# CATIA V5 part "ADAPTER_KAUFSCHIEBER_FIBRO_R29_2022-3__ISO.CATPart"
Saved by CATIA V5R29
Part number: ADAPTER_KAUFSCHIEBER_STARTPART
Revision: RELEASE@VERSION@1.0@02.03.2007
Property "Produktbezeichnung": "FCC AEC-HV 60-30°"
Property "Anzahl": 1
Property "Anzahl_spiegelbildlich": 0
Property "Werkstoff_Benennung": "1.1191"
Property "Rohmasse": 0 (mass)
Property "Zuschnittsmasse": 0 (mass)
Property "Fertigmasse": 0 (mass)
Property "Beschaffungsart": "B"
Property "ZSB_Blatt": 0
Property "Detail_Blatt": 0
Property "Lieferantenname": "FIBRO GmbH"
Property "Lieferantenauswahl": "bindend"
Property "Bestellnummer": "2016.24.006.30.2000.00"
Property "Waerme_Oberflaechenbehandlung": " "
Property "NC_Aenderung": "N"
Property "Ersatzteil": false
Property "Ersatzteil_k": 0
Property "Ersatzteil_s": 0
Property "Anfertigung": "A"
Property "Anfertigung_k": 0
Property "Anfertigung_s": 0
Property "Aenderungsindex": 0
Publications: "Axis_Referenz_in_Schieberrichtung", "Schieberdiagramm", "Fertigteil", "SCHIEBERKOERPER_SCHIEBERSTELLUNG_OFFEN_RELATIV_ZU_SCHIEBERBETT", "SCHIEBERKOERPER_SCHIEBERSTELLUNG_BEI_AUFTREFFEN_AUF_TREIBER", "SCHIEBERBETT_Fertigteil", "SCHIEBERBETT_Gussteil01_Anguss", "SCHIEBERBETT_Gussteil01_Fraesbearbeitung_1", "SCHIEBERBETT_Gussteil01_Fraesbearbeitung_2", "SCHIEBERBETT_Gussteil01_Bohrbearbeitung_1", "SCHIEBERBETT_Gussteil01_Bohrbearbeitung_2", "TREIBER_Fertigteil", "TREIBER_Gussteil02_Anguss", "TREIBER_Gussteil02_Fraesbearbeitung_1", "TREIBER_Gussteil02_Bohrbearbeitung_1", "TREIBER_Gussteil02_Bohrbearbeitung_2", "SCHIEBER_Montagefreiraum", "SCHIEBER_Bauraum", "INFO_Gewinde_Gussteil01", "INFO_D_Passbohrung_Gussteil01", "INFO_Tol_Passung_Gussteil01", "INFO_Gewinde_Gussteil02", "INFO_D_Passbohrung_Gussteil02", "INFO_Tol_Passung_Gusstei02", "INFO_Breite_Passfedernut_Gussteil01", "INFO_Tiefe_Passfedernut_Gussteil01", "INFO_Tol_Passfedernut_Gussteil01", "SCHIEBERBETT_BOHRSKETCH_GEWINDE", "SCHIEBERBETT_BOHRSKETCH_PASSUNGEN", "SCHIEBERBETT_BOHREBENE", "TREIBER_BOHRSKETCH_GEWINDE", "TREIBER_BOHRSKETCH_PASSUNGEN", "TREIBER_BOHREBENE", "SCHIEBERBETT_PASSFEDER", "INFO_Schieberwinkel", "INFO_Treiberwinkel", "INFO_Schieberhub", "INFO_Schieberart", "INFO_Produktbezeichnung", "INFO_Werkstoff_Benennung", "INFO_Rohmass", "INFO_Bestellnummer", "INFO_Lieferantenname", "INFO_Anzahl", "INFO_Rohmasse", "SKETCH_Passfeder1", "SKETCH_Passfeder2", "SKETCH_Passfeder3", "SKETCH_Passfeder4", "SCHIEBERKOERPER_BOHREBENE", "SCHIEBERKOERPER_BOHRSKETCH_AUSRICHTBOHRUNG", "SCHIEBERKOERPER_ZSB_Bearbeitung_Ausrichtflaeche", "SCHIEBERKOERPER_ZSB_Bearbeitung_Ausrichtbohrung"
Bounding box of the stored display mesh (mm): x 0 to 1950, y 0 to 429.656, z 0 to 1442.5
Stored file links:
  N:\B2\Normteile\K\2016\BAK_Adapter_2019\V_2019\ADAPTER_KAUFSCHIEBER_FIBRO_R29_2022-3__ISO.CATPart
  W:\KT_B5\Schneider_extern_47150\2007-02-12__Schieberadapter_alt\Kaufteilschieber_Stand_AK_07-08_11_2006\XX_XXX__ADAPTER_KAUFTEILSCHIEBER__123456789012.CATPart
  \\vhnfs271\ktkon\KT_B5\Schneider_extern_47150\2007-02-07__Adapter_Kaufteilschieber_R14\ADAPTER_KAUFTEILSCHIEBER_Vers11.CATPart
  N:\B2\Normteile\K\2016\BAK_Adapter_2019\V_2019\EXTRACT_INFO_PARAMETERS.xlsx
  N:\B2\Normteile\K\2016\24\CAD\V5\cm\260\2016.24.026.00.1000.00__CM.CATPart
  N:\B2\Normteile\K\2016\24\CAD\V5\cm\260\2016.24.026.75.1000.00__CM.CATPart
  N:\B2\Normteile\K\2016\24\CAD\V5\cm\260\2016.24.026.30.1000.00__CM.CATPart
  N:\B2\Normteile\K\2016\24\CAD\V5\cm\260\2016.24.026.65.1000.00__CM.CATPart
  N:\B2\Normteile\K\2016\15\008\cm\2016.15.008__CM__FCC_DM-HV_V00_ISO.CATPart
  N:\B2\Normteile\K\2016\15\008\cm\2016.15.008__CM__FCC_DM-HV.CATPart
  N:\B2\Normteile\K\2016\24\CAD\V5\cm\260\2016.24.026.45.1000.00__CM.CATPart
  N:\B2\Normteile\K\2016\24\CAD\V5\cm\220\2016.24.022.20.1000.00__CM.CATPart
  N:\B2\Normteile\K\2016\24\CAD\V5\cm\260\2016.24.026.40.1000.00__CM.CATPart
  N:\B2\Normteile\K\2016\24\CAD\V5\cm\260\2016.24.026.20.1000.00__CM.CATPart
  N:\B2\Normteile\K\2016\24\CAD\V5\cm\260\2016.24.026.10.1000.00__CM.CATPart
  N:\B2\Normteile\K\2016\24\CAD\V5\cm\260\2016.24.026.60.1000.00__CM.CATPart
  N:\B2\Normteile\K\2016\24\CAD\V5\cm\026\2016.24.026.10.1000.00__CM.CATPart
  N:\B2\Normteile\K\2016\24\CAD\V5\cm\008\2016.24.008.75.1000.00__CM.CATPart
  G:\Produkte\pg_k\2016\2016_25__neu_ab_GJ_2018\V5\cm\070\2016.25.07x.05.x000.02__CM.CATPart
  N:\B2\Normteile\K\2016\24\CAD\V5\cm\006\2016.24.006.30.2000.00__CM.CATPart
  N:\B2\Normteile\K\2016\15\016\cm\2016.15.016__CM__FCC_DM-HV_V00_ISO.CATPart
  N:\B2\Normteile\K\2016\15\016\cm\2016.15.016__CM__FCC_DM-HV.CATPart
  N:\B2\Normteile\K\2016\24\CAD\V5\cm\011\2016.24.011.10.1000.00__CM.CATPart
  N:\B2\Normteile\K\2016\24\CAD\V5\022\cm_parametric\2016.24.022__CM__FCC_AEC-HV__ADAPTER_COMPATIBLE.CATPart
  N:\B2\Normteile\K\2016\24\CAD\V5\026\cm_parametric\2016.24.026__CM__FCC_AEC-HV__ADAPTER_COMPATIBLE.CATPart
  N:\B2\Normteile\K\2016\24\CAD\V5\033\cm_parametric\2016.24.033__CM__FCC_AEC-HV__ADAPTER_COMPATIBLE.CATPart
  N:\B2\Normteile\K\2016\24\CAD\V5\040\cm_parametric\2016.24.040__CM__FCC_AEC-HV__ADAPTER_COMPATIBLE.CATPart
  N:\B2\Normteile\K\2016\24\CAD\V5\050\cm_parametric\2016.24.050__CM__FCC_AEC-HV__ADAPTER_COMPATIBLE.CATPart
  N:\B2\Normteile\K\2016\24\CAD\V5\060\cm_parametric\2016.24.060__CM__FCC_AEC-HV__ADAPTER_COMPATIBLE.CATPart
  N:\B2\Normteile\K\2016\24\CAD\V5\006\cm_parametric\2016.24.006__CM__FCC_AEC-HV__V00_ISO.CATPart
  N:\B2\Normteile\K\2016\15\011\cm\2016.15.011__CM__FCC_DM-HV.CATPart
  N:\B2\Normteile\K\2016\15\022\cm\2016.15.022__CM__FCC_DM-HV.CATPart
  N:\B2\Normteile\K\2016\15\031\cm\2016.15.031__CM__FCC_DM-HV.CATPart
  N:\B2\Normteile\K\2016\15\040\cm\2016.15.040__CM__FCC_DM-HV.CATPart
  G:\SApp\Anwendungsberatung\210224__BMW_ZSB_Ausrichtbohrung\CAD\ADAPTER_KAUFSCHIEBER_FIBRO_R28_2021__BETA_A_STEP1.CATPart
  N:\B2\Normteile\K\2016\24\CAD\V5\008\cm_parametric\2016.24.008__CM__FCC_AEC-HV__V00_ISO.CATPart
  N:\B2\Normteile\K\2016\24\CAD\V5\033\cm_parametric\2016.24.033__CM__FCC_AEC-HV__V00_ISO.CATPart
  N:\B2\Normteile\K\2016\15\008\cm\2016.15.008__CM__FCC_DM-HV_V02_ISO.CATPart
  N:\B2\Normteile\K\2016\15\011\cm\2016.15.011__CM__FCC_DM-HV_V02_ISO.CATPart
  N:\B2\Normteile\K\2016\15\016\cm\2016.15.016__CM__FCC_DM-HV_V02_ISO.CATPart
  N:\B2\Normteile\K\2016\15\022\cm\2016.15.022__CM__FCC_DM-HV_V02_ISO.CATPart
  N:\B2\Normteile\K\2016\15\031\cm\2016.15.031__CM__FCC_DM-HV_V02_ISO.CATPart
  N:\B2\Normteile\K\2016\15\040\cm\2016.15.040__CM__FCC_DM-HV_V02_ISO.CATPart
  N:\B2\Normteile\K\2016\24\CAD\V5\011\cm_parametric\2016.24.011__CM__FCC_AEC-HV__V00_ISO.CATPart
  N:\B2\Normteile\K\2016\24\CAD\V5\015\cm_parametric\2016.24.015__CM__FCC_AEC-HV__V00_ISO.CATPart
  N:\B2\Normteile\K\2016\24\CAD\V5\018\cm_parametric\2016.24.018__CM__FCC_AEC-HV__V00_ISO.CATPart
  N:\B2\Normteile\K\2016\24\CAD\V5\022\cm_parametric\2016.24.022__CM__FCC_AEC-HV__V00_ISO.CATPart
  N:\B2\Normteile\K\2016\24\CAD\V5\026\cm_parametric\2016.24.026__CM__FCC_AEC-HV__V00_ISO.CATPart
  N:\B2\Normteile\K\2016\24\CAD\V5\040\cm_parametric\2016.24.040__CM__FCC_AEC-HV__V00_ISO.CATPart
  N:\B2\Normteile\K\2016\24\CAD\V5\050\cm_parametric\2016.24.050__CM__FCC_AEC-HV__V00_ISO.CATPart
  N:\B2\Normteile\K\2016\24\CAD\V5\060\cm_parametric\2016.24.060__CM__FCC_AEC-HV__V00_ISO.CATPart
  N:\B2\Normteile\K\2016\25  #neu_ab_GJ_2018#\V5\cm\070\2016.25.07x.00.x000.02__CM.CATPart
  N:\B2\Normteile\K\2016\25  #neu_ab_GJ_2018#\V5\cm\070\2016.25.07x.05.x000.02__CM.CATPart
  N:\B2\Normteile\K\2016\25  #neu_ab_GJ_2018#\V5\cm\070\2016.25.07x.10.x000.02__CM.CATPart
  N:\B2\Normteile\K\2016\25  #neu_ab_GJ_2018#\V5\cm\070\2016.25.07x.15.x000.02__CM.CATPart
  N:\B2\Normteile\K\2016\25  #neu_ab_GJ_2018#\V5\cm\070\2016.25.07x.20.x000.02__CM.CATPart
  N:\B2\Normteile\K\2016\25  #neu_ab_GJ_2018#\V5\cm\070\2016.25.07x.25.x000.02__CM.CATPart
  N:\B2\Normteile\K\2016\25  #neu_ab_GJ_2018#\V5\cm\070\2016.25.07x.30.x000.02__CM.CATPart
  N:\B2\Normteile\K\2016\25  #neu_ab_GJ_2018#\V5\cm\070\2016.25.07x.35.x000.02__CM.CATPart
  N:\B2\Normteile\K\2016\25  #neu_ab_GJ_2018#\V5\cm\070\2016.25.07x.40.x000.02__CM.CATPart
  N:\B2\Normteile\K\2016\25  #neu_ab_GJ_2018#\V5\cm\070\2016.25.07x.45.x000.02__CM.CATPart
  N:\B2\Normteile\K\2016\25  #neu_ab_GJ_2018#\V5\cm\070\2016.25.07x.50.x000.02__CM.CATPart
  N:\B2\Normteile\K\2016\25  #neu_ab_GJ_2018#\V5\cm\070\2016.25.07x.55.x000.02__CM.CATPart
  N:\B2\Normteile\K\2016\25  #neu_ab_GJ_2018#\V5\cm\070\2016.25.07x.60.x000.02__CM.CATPart
  N:\B2\Normteile\K\2016\25  #neu_ab_GJ_2018#\V5\cm\070\2016.25.07x.65.x000.02__CM.CATPart
  N:\B2\Normteile\K\2016\25  #neu_ab_GJ_2018#\V5\cm\070\2016.25.07x.70.x000.02__CM.CATPart
  N:\B2\Normteile\K\2016\25  #neu_ab_GJ_2018#\V5\cm\070\2016.25.07x.75.x000.02__CM.CATPart
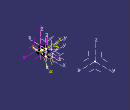
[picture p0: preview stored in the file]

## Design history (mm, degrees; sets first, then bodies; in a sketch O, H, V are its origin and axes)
Parameters
  Variante = "2016.24.006.30.2000.00" {= External.id_number}
  INFO_Version_Ausgabe = "2022-3" {design table}
  INFO_Schieberhub = 30 mm {design table}
  INFO_Winkel_Arbeitsrichtung = 30 deg {design table}
  INFO_Winkel_Alpha = 60 deg {design table}
  INFO_Passfeder_im_Lieferumfang = true {design table}
  INFO_Winkel_Treiber = 30 deg {design table}
  INFO_Winkel_Schieberbett = 30 deg {design table}
  INFO_Schieberart = "oben" {design table}
  group "Anschlussgeometrie"
    FP_Aufmass = 10 mm
    group "Schieberbett"
      cb_l = 205 mm {design table}
      cb_w = 60 mm {design table}
      cb_backup_thrust = true {design table}
      cb_clearance_backup_thrust = true {design table}
      FP_cb_Ueberstand_Spiegel = 15 mm
      FP_cb_Kraftabfangung = "Gussschulter"
      FP_cb_Hoehe_Schulter = 110 mm {design table}
      FP_cb_Breite_Schulter = 60 mm {design table}
      FP_cb_Freimachung_Schulter = "mit Freimachung"
      FP_cb_Gewindetiefe = 18 mm {design table}
      FP_cb_Gewindeauslauf = 8.3 mm {design table}
      FP_cb_Tiefe_Passbohrung = 15 mm {design table}
      FP_cb_Verlaengerung_Fraesung_Passfeder_laengs = 0 mm
      FP_cb_Verlaengerung_Fraesung_Passfeder_quer = 20 mm
      FP_cb_Fraeshoehe = 100 mm
    group "Treiber"
      cd_l = 125 mm {design table}
      cd_w = 60 mm {design table}
      cd_backup_thrust = true {design table}
      cd_clearance_backup_thrust = true {design table}
      FP_cd_Ueberstand_Spiegel = 10 mm
      FP_cd_Kraftabfangung = "Gussschulter"
      FP_cd_Hoehe_Schulter = 22 mm {design table}
      FP_cd_Breite_Schulter = 60 mm {design table}
      FP_cd_Freimachung_Schulter = "mit Freimachung"
      FP_cd_Gewindetiefe = 15 mm {design table}
      FP_cd_Gewindeauslauf = 7.3 mm {design table}
      FP_cd_Tiefe_Passbohrung = 15 mm {design table}
      FP_cd_Verlaengerung_Fraesung_Passfeder_quer = 20 mm
      FP_cd_Fraeshoehe = 100 mm
  group "Bohrbearbeitung"
    INFO_Gewinde_Gussteil01 = "M12" {design table}
    INFO_D_Passbohrung_Gussteil01 = 10 mm {design table}
    INFO_Tol_Passung_Gussteil01 = "H7" {design table}
    INFO_Gewinde_Gussteil02 = "M10" {design table}
    INFO_D_Passbohrung_Gussteil02 = 10 mm {design table}
    INFO_Tol_Passung_Gusstei02 = "H7" {design table}
  group "Fraesbearbeitung"
    INFO_Breite_Passfedernut_Gussteil01 = 25 mm {design table}
    INFO_Tiefe_Passfedernut_Gussteil01 = 10 mm {design table}
    INFO_Tol_Passfedernut_Gussteil01 = "H7" {design table}
  group "ZSB_Referenzbohrung"
    arx = 200 mm {design table}
    ary = 24 mm {design table}
    arz = 20 mm {design table}
  group "Translation_Schiebereinheit"
    External.Translation_Schiebereinheit_in_X = 0 mm
    External.Translation_Schiebereinheit_in_Y = 0 mm
    External.Translation_Schiebereinheit_in_Z = 0 mm
  group "Stueckliste"
    Positionsnummer = ""
    Identnummer = ""
    Produktbezeichnung = "FCC AEC-HV 60-30°" {design table}
    Anzahl = 1
    Anzahl_spiegelbildlich = 0
    Materialgruppe = ""
    Bemerkungskuerzel = ""
    Werkstoff_ID = ""
    Werkstoff_Benennung = "1.1191" {design table}
    Rohmass = "" {design table}
    Zuschnittsmass = ""
    Fertigmass = ""
    Rohmasse = 0 (mass) {design table}
    Zuschnittsmasse = 0 (mass)
    Fertigmasse = 0 (mass)
    Beschaffungsart = "B"
    DIN_ISO_Norm = ""
    Euro_Norm = ""
    Bauvorschrift_bzw_Werks_oder_Norm_Blatt = ""
    Lagernummer = ""
    Bezugsort = ""
    ZSB_Blatt = 0
    Detail_Blatt = 0
    Lieferantenname = "FIBRO GmbH"
    Lieferantennummer = ""
    Lieferantenauswahl = "bindend"
    Preiskategorie = ""
    Bestellnummer = "2016.24.006.30.2000.00" {= External.id_number}
    Sachmerkmale = ""
    Waerme_Oberflaechenbehandlung = " "
    Zusatzinfo = "" {design table}
    Hinweis = ""
    Verbaut_an_Pos_Nr = ""
    Symmetrie = ""
    NC_Aenderung = "N"
    Ersatzteil = false
    Ersatzteil_k = 0
    Ersatzteil_s = 0
    Anfertigung = "A"
    Anfertigung_k = 0
    Anfertigung_s = 0
    Langlaeufer = ""
    Aenderungsindex = 0
  group "Parameter_Schieberhersteller"
    factor = 1 {design table}
    sp = 30 mm {design table}
    ss = 30 mm {design table}
    cb_kl_h = 19 mm {design table}
    cb_kl_t = 10 mm {design table}
    cb_kl_l = 59 mm {design table}
    cb_kl1_x = 50 mm {design table}
    cb_kl1_activity = false {design table}
    cb_kl2_x = 100 mm {design table}
    cb_kl2_activity = false {design table}
    cb_kc_l = 59 mm {design table}
    cb_kc1_x = 62.5 mm {design table}
    cb_kc1_y = 0 mm {design table}
    cb_kc2_activity = false {design table}
    cd_kc_l = 50 mm {design table}
    cd_kc1_x = 30 mm {design table}
    cd_kc1_y = 35 mm {design table}
    cd_kc1_activity = false {design table}
    cd_kc2_activity = false {design table}
    type = "aerial cam unit" {design table}
    change_description = "assembly reference hole added, 2016.26 series added"
External parameters (linked from other documents)
  External.id_number = "2016.24.006.30.2000.00"
AxisSystem1 "Absolute Axis System": origin (0, 0, 0), X (1, 0, 0), Y (0, 1, 0), Z (0, 0, 1)
TTRSSet1
f4a2d38f3ddc11d3a929006094b99c4b_11 "CATTPSSet"
Set1 "ELEMENTE_FUER_REPLACE"
  AxisSystem2 "Dummy_AP_Axis_zum_Ersetzen": origin (1700, 0, 1200), X (1, 0, 0), Y (0, 1, 0), Z (0, 0, 1)
  Line1 "Dummy_Schieberrichtung_zum_Ersetzen": stored without definition
  AxisSystem3 "Axis_Horizontal_im_Einfuegepunkt_zum_Ersetzen": origin (1850, 180, 1312), X (0, 1, 0), Y (-1, 0, 0), Z (0, 0, 1)
  AxisSystem4 "Axis_Schieberrichtung_im_Einfuegepunkt_zum_Ersetzen": origin (1850, 180, 1312), X (0, 0.5, -0.866), Y (-1, 0, 0), Z (0, 0.866, 0.5)
Set2 "HILFSELEMENTE_POSITIONIERUNG"
  Plane1 "Plane_Hoehe_Einfuegepunkt_Schieber_zu_AP": type Offset, RefPlane XY plane of AxisSystem2, Offset 112
  Sketch1 "Sketch_Lage_Einfuegepunkt_Schieber_in_XOY" on Plane1, origin (1700, 0, 1312), H (1, 0, 0), V (0, 1, 0)
    point P1 (150, 180)
    line L1 (150, 280) -> (150, 80)
    reference projected line E1 (0, 0) -> (0, 246.2019) from Line1
    distance P1 H = 180
    distance P1 V = 150
    length L1 = 200
    midpoint: P1 L1
    parallelism: L1 E1
  Point1 "Absolute_Origin_Schiebereinheit": (0 {= External.Translation_Schiebereinheit_in_X}, 0 {= External.Translation_Schiebereinheit_in_Y}, 0 {= External.Translation_Schiebereinheit_in_Z})
  AxisToAxis1 "Lokale_Origin_Schiebereinheit": ToTransfor Point1, AxisOrigin AxisSystem1, Axis AxisSystem4
Set3 "HILFSELEMENTE_ACHSEN"
  Line2 "Schieberrichtung": type Angle, RefPoint vertex [YZ plane of AxisSystem3 | ZX plane of AxisSystem3 | XY plane of AxisSystem3], Curve edge [XY plane of AxisSystem3 | ZX plane of AxisSystem3], Support ZX plane of AxisSystem3, Start 0, End 20, Angle -30 {= -INFO_Winkel_Treiber}
  Line3 "Y-Richtung": type Normal, RefPoint vertex [YZ plane of AxisSystem3 | ZX plane of AxisSystem3 | XY plane of AxisSystem3], RefSkin ZX plane of AxisSystem3, Start 0, End 20
Set4 "ACHSENSYSTEME_REFERENZ_SCHIEBERHERSTELLER"
  AxisSystem5 "Axis_Referenz_in_Schieberrichtung": origin (1850, 180, 1312), X (0, 0.5, -0.866), Y (-1, 0, 0), Z (0, 0.866, 0.5)
  Line4 "X-Richtung_Axis_Referenz_horizontal": type Angle, RefPoint vertex [YZ plane of AxisSystem5 | ZX plane of AxisSystem5 | XY plane of AxisSystem5], Curve edge [ZX plane of AxisSystem5 | YZ plane of AxisSystem5], Support ZX plane of AxisSystem5, Start 0, End 20, Angle 30 {= INFO_Winkel_Arbeitsrichtung}
  AxisSystem6 "Axis_Referenz_horizontal": origin (1850, 180, 1312), X (0, 1, 0), Y (-1, 0, 0), Z (0, 0, 1)
Set5 "Diagramm"
  Sketch2 "Schieberdiagramm" on ZX plane of AxisSystem6, origin (1850, 180, 1312), H (0, 1, 0), V (0, 0, 1), geometry linked from another document
Set6 "SCHIEBERKOERPER_HILFSELEMENTE"
  Set7 "reference elements"
    Set8 "origin"
      AxisSystem7: origin (-25, 0, 210), X (1, 0, 0), Y (0, -1, 0), Z (0, 0, -1)
      AxisSystem8: origin (136.258, 0, 88.5), X (-0.5, 0, -0.866), Y (0, -1, 0), Z (-0.866, 0, 0.5)
      AxisSystem9: origin (0, 0, 0), X (-1, 0, 0), Y (0, -1, 0), Z (0, 0, 1)
    Set9 "translated"
      AxisToAxis2 "cam base": ToTransfor AxisSystem7, AxisOrigin AxisSystem8, Axis AxisSystem5
      AxisToAxis3 "cam driver": ToTransfor AxisSystem9, AxisOrigin AxisSystem8, Axis AxisSystem5
      AxisToAxis4 "sp_assembly_reference_hole_tr": ToTransfor sketch element, AxisOrigin AxisSystem8, Axis AxisSystem5
    Set10 "relative positions"
      Line5 "spring direction": type Angle, RefPoint vertex [YZ plane of AxisSystem5 | ZX plane of AxisSystem5 | XY plane of AxisSystem5], Curve Line4, Support ZX plane of AxisSystem5, Start 0, End 30 {= ss}, Angle 30 {= factor *INFO_Winkel_Schieberbett}
      Translate1 "1": Direction edge [ZX plane of AxisSystem6 | YZ plane of AxisSystem6], Length 30 {= factor *sp}, ToTransfor vertex [YZ plane of AxisSystem6 | ZX plane of AxisSystem6 | XY plane of AxisSystem6]
      Translate2 "3": Direction Line5, Length 30 {= ss}, ToTransfor Translate1
    Set11 "PMI"
      Extract1 "anchor point": ExtractElem vertex [YZ plane of AxisSystem6 | ZX plane of AxisSystem6 | XY plane of AxisSystem6]
      Plane2 "support plane": type OffsetPt, RefPlane ZX plane of AxisSystem6, RefPoint Extract1
      Line6 "orientation": type PtDir, RefPoint Extract1, Direction edge [XY plane of AxisSystem6 | ZX plane of AxisSystem6], Start -50, End 50
    Set12 "Bezugselemente ZSB-Bearbeitung step1"
      Plane3 "PLN_milling_assembly_refrence_hole step1": type Offset, RefPlane XY plane of AxisSystem9, Offset 20 {= arz}
      Sketch3 "assembly_reference_hole" on Plane3, origin (0, 0, 20), H (0, -1, 0), V (-1, 0, 0)
        point P1 (24, -200)
        point P2 (-24, -200)
        construction circle A1 centre (24, -200) radius 4
        point P3 (24, -200)
        distance V P1 = 24 {= ary}
        distance H P1 = 200 {= arx}
        radius A1 = 4
        symmetry: P1 P2 V
        coincidence: P3 P1
Set13 "SCHIEBERKOERPER_BOHRSKIZZEN_UND_BOHREBENEN"
  AxisToAxis5 "SCHIEBERKOERPER_BOHREBENE": ToTransfor Plane3, AxisOrigin AxisSystem8, Axis AxisSystem5
  Sketch4 "SCHIEBERKOERPER_BOHRSKETCH_AUSRICHTBOHRUNG" on AxisToAxis5, origin (1850, 316.258, 1243.5), H (1, 0, 0), V (0, 1, 0), geometry linked from another document
Set14 "SCHIEBERBETT_HILFSELEMENTE"
  Set15 "interface"
    DatumPoint1 "Result of sp_screw_base": linked copy from another document
    DatumPoint2 "Result of sp_pin_base": linked copy from another document
    AxisToAxis6 "sp_screw_base": ToTransfor DatumPoint1, AxisOrigin AxisSystem8, Axis AxisSystem5
    AxisToAxis7 "sp_pin_base": ToTransfor DatumPoint2, AxisOrigin AxisSystem8, Axis AxisSystem5
    Sketch5 "key positions along" on Plane4, origin (1850, 341.258, 1433.5), H (0, 1, 0), V (-1, 0, 0)
      point P1 (-50, 0)
      point P2 (-100, 0)
      distance V P1 = 50 {= cb_kl1_x}
      distance P2 V = 100 {= cb_kl2_x}
      coincidence: P1 H, P2 H
    Sketch6 "key positions cross" on Plane4, origin (1850, 341.258, 1433.5), H (0, 1, 0), V (-1, 0, 0)
      point P1 (-62.5, 0)
      point P2 (-62.5, 0)
      distance V P1 = 62.5 {= cb_kc1_x}
      distance H P1 = 0 {= cb_kc1_y}
      symmetry: P1 P2 H
Set16 "SCHIEBERBETT_BOHRSKIZZEN_UND_BOHREBENEN"
  Plane4 "SCHIEBERBETT_BOHREBENE": type OffsetPt, RefPlane face of AxisToAxis2, RefPoint vertex [face of AxisToAxis2 | face of AxisToAxis2 | face of AxisToAxis2]
  Sketch7 "SCHIEBERBETT_BOHRSKETCH_GEWINDE" on face of AxisToAxis2, origin (1850, 341.258, 1433.5), H (0, 1, 0), V (-1, 0, 0), geometry linked from another document
  Sketch8 "SCHIEBERBETT_BOHRSKETCH_PASSUNGEN" on face of AxisToAxis2, origin (1850, 341.258, 1433.5), H (0, 1, 0), V (-1, 0, 0), geometry linked from another document
Set17 "TREIBER_HILFSELEMENTE"
  Set18 "interface"
    DatumPoint3 "Result of sp_screw_driver": linked copy from another document
    DatumPoint4 "Result of sp_pin_driver": linked copy from another document
    AxisToAxis8 "sp_screw_driver": ToTransfor DatumPoint3, AxisOrigin AxisSystem8, Axis AxisSystem5
    AxisToAxis9 "sp_pin_driver": ToTransfor DatumPoint4, AxisOrigin AxisSystem8, Axis AxisSystem5
    Sketch9 "key positions cross" on Plane5, origin (1850, 316.258, 1223.5), H (0, -1, 0), V (-1, 0, 0)
      point P1 (30, -35)
      point P2 (30, 35)
      distance V P1 = 30 {= cd_kc1_x}
      distance H P1 = 35 {= cd_kc1_y}
      symmetry: P1 P2 H
Set19 "TREIBER_BOHRSKIZZEN_UND_BOHREBENEN"
  Plane5 "TREIBER_BOHREBENE": type OffsetPt, RefPlane face of AxisToAxis3, RefPoint vertex [face of AxisToAxis3 | face of AxisToAxis3 | face of AxisToAxis3]
  Sketch10 "TREIBER_BOHRSKETCH_GEWINDE" on face of AxisToAxis3, origin (1850, 316.258, 1223.5), H (0, -1, 0), V (-1, 0, 0), geometry linked from another document
  Sketch11 "TREIBER_BOHRSKETCH_PASSUNGEN" on face of AxisToAxis3, origin (1850, 316.258, 1223.5), H (0, -1, 0), V (-1, 0, 0), geometry linked from another document
Body1 "SCHIEBERKOERPER_Fertigteil" (main body)
  Body2 "Rohteil"
    Body3 "Grundkoerper"
      Body4 "Result of cam slider"
        Solid1: linked copy from another document
      Assemble1: tool Body4
      AxisToAxis10: ToTransfor Assemble1, AxisOrigin AxisSystem8, Axis AxisSystem5
    Add1 "Grundkoerper": tool Body3
    Body5 "Gusskorrektur_Abzug"
    Remove1 "Gusskorrektur_Abzug": tool Body5
    Body6 "Gusskorrektur_Anguss"
    Add2 "Gusskorrektur_Anguss": tool Body6
    Body7 "Gusskorrektur_Freiguss"
    Remove2 "Gusskorrektur_Freiguss": tool Body7
    Body8 "Bearbeitungszugaben"
    Add3 "Bearbeitungszugaben": tool Body8, deactivated
  Add4 "Rohteil": tool Body2
  Body9 "Fraesbearbeitung"
  Remove3 "Fraesbearbeitung": tool Body9
  Body10 "Bohrbearbeitung"
  Remove4 "Bohrbearbeitung": tool Body10
  Body11 "ZSB_Bearbeitung"
  Remove5 "ZSB_Bearbeitung": tool Body11
Body12 "SCHIEBERKOERPER_SCHIEBERSTELLUNG_OFFEN_RELATIV_ZU_SCHIEBERBETT"
  Body13 "Result of SCHIEBERKOERPER_Fertigteil"
    Solid2: linked copy from another document
  Add5: tool Body13
  Translate3 "translate.1": Direction Line5, Length 30 {= ss}, ToTransfor Add5
Body14 "SCHIEBERKOERPER_SCHIEBERSTELLUNG_BEI_AUFTREFFEN_AUF_TREIBER"
  Body15 "Result of SCHIEBERKOERPER_Fertigteil"
    Solid3: linked copy from another document
  Add6: tool Body15
  Translate4 "translate.2": FirstPoint vertex [YZ plane of AxisSystem6 | ZX plane of AxisSystem6 | XY plane of AxisSystem6], SecondPoint Translate2, ToTransfor Add6
Body16 "SCHIEBERKOERPER_ZSB_Bearbeitung_Ausrichtflaeche"
  Sketch12 on AxisToAxis5, origin (1826, 116.258, 1243.5), H (-1, 0, 0), V (0, 1, 0)
    line L1 (-4.5, -45) -> (20.5, -45)
    line L2 (20.5, -45) -> (20.5, 25)
    line L3 (20.5, 25) -> (-4.5, 25)
    line L4 (-4.5, 25) -> (-4.5, -45)
    distance L4 V = 4.5
    horizontal: L1 H, L3 H
    vertical: L2 V, L4 V
  Pocket1: profile Sketch12, direction (0, 0, -1), length 20
  Fillet1: radius 13, on edge [face of Pocket1 from Sketch12.L4 | face of Pocket1 from Sketch12.L3]
  Mirror1: of the body so far, about face of AxisToAxis3
Body17 "SCHIEBERKOERPER_ZSB_Bearbeitung_Ausrichtbohrung"
  Sketch13 on AxisToAxis5, origin (1826, 116.258, 1243.5), H (1, 0, 0), V (0, 1, 0)
    point P1 (0, 0)
    coincidence: O P1
  Hole1: placed by Sketch13, at (1826, 116.258, 1243.5) direction (0, 0, 1), diameter 8, depth 15, V-bottom angle 120
  UserPattern1: of the body so far, copies 2, at the points of Sketch4
Body18 "SCHIEBERBETT_Fertigteil"
  Body19 "Result of cam base"
    Solid4: linked copy from another document
  Assemble2: tool Body19
  AxisToAxis11: ToTransfor Assemble2, AxisOrigin AxisSystem8, Axis AxisSystem5
Body20 "SCHIEBERBETT_PASSFEDER"
  Sketch14 on ZX plane of AxisSystem5, origin (1850, 180, 1312), H (0, 0.866, 0.5), V (0, 0.5, -0.866)
    line L1 (2, 0.5) -> (2.866, 0)
    point P2 (2.866, 0)
    line L2 (2.866, 0) -> (2, -0.5)
    line L3 (2, -0.5) -> (2, 0.5)
    reference projected line E1 through (0, 0) direction (0, 1) from edge [XY plane of AxisSystem5 | ZX plane of AxisSystem5]
    reference projected line E2 through (0, 0) direction (1, 0) from edge [ZX plane of AxisSystem5 | YZ plane of AxisSystem5]
    length L3 = 1
    length L2 = 1
    length L1 = 1
    distance L3 E1 = 2
    vertical: L3 V
    coincidence: P2 E2
  Shaft1 "Dummy_Passfeder": profile Sketch14, axis Sketch14.L3, angle 360, deactivated
  Sketch15 "SKETCH_Passfeder1" on Plane4, origin (1850, 291.258, 1433.5), H (0, 1, 0), V (-1, 0, 0)
    line L1 (-29.5, 0) -> (29.5, 0)
    length L1 = 59 {= cb_kl_l}
    midpoint: L1 O
    horizontal: L1 H
  Pad1: profile Sketch15, direction (0, 0, 1), length 9 {= cb_kl_h-cb_kl_t}, opposite side length 10 {= cb_kl_t}, thin wall 25 {= INFO_Breite_Passfedernut_Gussteil01}, deactivated
  Sketch16 "SKETCH_Passfeder2" on Plane4, origin (1850, 241.258, 1433.5), H (0, 1, 0), V (-1, 0, 0)
    line L1 (-29.5, 0) -> (29.5, 0)
    length L1 = 59 {= cb_kl_l}
    midpoint: L1 O
    horizontal: L1 H
  Pad2: profile Sketch16, direction (0, 0, 1), length 9 {= cb_kl_h-cb_kl_t}, opposite side length 10 {= cb_kl_t}, thin wall 25 {= INFO_Breite_Passfedernut_Gussteil01}, deactivated
  Sketch17 "SKETCH_Passfeder3" on Plane4, origin (1850, 278.758, 1433.5), H (0, 1, 0), V (-1, 0, 0)
    line L1 (0, -29.5) -> (0, 29.5)
    length L1 = 59 {= cb_kc_l}
    midpoint: L1 O
    vertical: L1 V
  Pad3: profile Sketch17, direction (0, 0, 1), length 9 {= cb_kl_h-cb_kl_t}, opposite side length 10 {= cb_kl_t}, thin wall 25 {= INFO_Breite_Passfedernut_Gussteil01}
  Sketch18 "SKETCH_Passfeder4" on Plane4, origin (1850, 278.758, 1433.5), H (0, 1, 0), V (-1, 0, 0)
    line L1 (0, -29.5) -> (0, 29.5)
    length L1 = 59 {= cb_kc_l}
    midpoint: L1 O
    vertical: L1 V
  Pad4: profile Sketch18, direction (0, 0, 1), length 9 {= cb_kl_h-cb_kl_t}, opposite side length 10 {= cb_kl_t}, thin wall 25 {= INFO_Breite_Passfedernut_Gussteil01}, deactivated
Body21 "SCHIEBERBETT_Gussteil01_Anguss"
  Sketch19 on face of AxisToAxis2, origin (1850, 341.258, 1433.5), H (0, 1, 0), V (0, 0, -1)
    point P1 (15, 0)
    point P2 (-220, 0)
    line L1 (-220, 0) -> (15, 0)
    distance P1 V = 15 {= FP_cb_Ueberstand_Spiegel}
    distance V P2 = 220 {= cb_l+FP_cb_Ueberstand_Spiegel}
    horizontal: L1 H
    coincidence: H L1
  Pad5: profile Sketch19, direction (-1, 0, 0), length 45 {= cb_w/2+FP_cb_Ueberstand_Spiegel}, mirrored extent, thin wall 10 {= FP_Aufmass}, second thickness 50
  Chamfer1: length 20 {= FP_cb_Ueberstand_Spiegel +5mm}, angle 45, on edge [face of Pad5 | end face of Pad5] (x2); edge [start face of Pad5 | face of Pad5] (x2)
  Thickness1 "manuelle Korrektur vorn": Face face of Pad5, Thickness 0
  Thickness2 "manuelle Korrektur seitlich": Face (end face of Pad5; start face of Pad5), Thickness 0
  Thickness3 "manuelle Korrektur hinten": Face face of Pad5, Thickness 0
  Body22 "Gussschulter"
    Sketch20 on face of AxisToAxis2, origin (1850, 341.258, 1323.5), H (0, 1, 0), V (0, 0, -1)
      point P1 (0, -50)
      point P2 (0, -170)
      line L1 (0, -170) -> (0, -50)
      distance P2 H = 170 {= FP_cb_Hoehe_Schulter+60mm}
      distance P1 H = 50
      coincidence: V L1
      vertical: L1 V
    Sketch21 on face of AxisToAxis2, origin (1850, 341.258, 1433.5), H (0, 1, 0), V (0, 0, -1)
      point P1 (0, -50)
      point P2 (0, 110)
      line L1 (0, 110) -> (0, -50)
      distance P1 H = 50
      distance H P2 = 110 {= FP_cb_Hoehe_Schulter}
      coincidence: V L1
      vertical: L1 V
    Pad6: profile Sketch21, direction (-1, 0, 0), length 30 {= FP_cb_Breite_Schulter /2}, mirrored extent, thin wall 10 {= FP_Aufmass}, second thickness 60
    Pocket2: profile Sketch20, direction (1, 0, 0), through (limit type 3), opposite side through (limit type 3), thin wall 20, second thickness 50
  Assemble3 "Gussschulter": tool Body22
Body23 "SCHIEBERBETT_Gussteil01_Fraesbearbeitung_1"
  Body24
    Sketch22 on face of AxisToAxis2, origin (1850, 341.258, 1433.5), H (0, 1, 0), V (0, 0, -1)
      point P1 (0, 0)
      point P2 (-230, 0)
      line L1 (-230, 0) -> (0, 0)
      distance V P2 = 230 {= cb_l+FP_cb_Ueberstand_Spiegel +10mm}
      horizontal: L1 H
      coincidence: H L1, V P1
    Pocket3: profile Sketch22, direction (1, 0, 0), length 60 {= cb_w /2+FP_cb_Ueberstand_Spiegel +15mm}, mirrored extent, thin wall 110 {= FP_Aufmass + FP_cb_Fraeshoehe}
    Fillet2: radius 20, on edge [end face of Pocket3 | face of Pocket3] (x2); edge [face of Pocket3 | start face of Pocket3] (x2)
  Assemble4: tool Body24
  Body25
    Sketch23 on face of AxisToAxis2, origin (1850, 341.258, 1433.5), H (0, 1, 0), V (0, 0, -1)
      point P1 (0, 0)
      point P2 (0, 120)
      line L1 (0, 120) -> (0, 0)
      distance H P2 = 120 {= FP_cb_Hoehe_Schulter +10mm}
      coincidence: V P1
      vertical: L1 V
    Pocket4: profile Sketch23, direction (1, 0, 0), length 60 {= FP_cb_Breite_Schulter  /2+FP_cb_Ueberstand_Spiegel +15mm}, mirrored extent, thin wall 30 {= FP_Aufmass +20mm}
    Fillet3: radius 20, on edge [start face of Pocket4 | face of Pocket4]; edge [face of Pocket4 | end face of Pocket4]
  Assemble5: tool Body25
Body26 "SCHIEBERBETT_Gussteil01_Fraesbearbeitung_2"
  Sketch24 on ZX plane of AxisSystem5, origin (1850, 180, 1312), H (0, 0.866, 0.5), V (0, 0.5, -0.866)
    line L1 (2, 0.5) -> (2.866, 0)
    point P2 (2.866, 0)
    line L2 (2.866, 0) -> (2, -0.5)
    line L3 (2, -0.5) -> (2, 0.5)
    length L3 = 1
    length L2 = 1
    length L1 = 1
    distance L3 V = 2
    coincidence: P2 H
    vertical: L3 V
  Groove1 "Dummy_Passfedernut": profile Sketch24, axis Sketch24.L3, angle 360, deactivated
  Body27 "key.1"
    Pocket5: profile Sketch15, direction (0, 0, 1), length 10 {= INFO_Tiefe_Passfedernut_Gussteil01}, thin wall 25 {= INFO_Breite_Passfedernut_Gussteil01}
    Thickness4: Face (face of Pocket5; face of Pocket5), Thickness 12 {= (INFO_Breite_Passfedernut_Gussteil01 -1mm)/2+FP_cb_Verlaengerung_Fraesung_Passfeder_laengs}
    Fillet4: radius 12 {= (INFO_Breite_Passfedernut_Gussteil01 -1mm)/2}, on edge [face of Pocket5 | face of Pocket5] (x4)
  Assemble6 "key.1": tool Body27, deactivated
  Body28 "key.2"
    Pocket6: profile Sketch16, direction (0, 0, 1), length 10 {= INFO_Tiefe_Passfedernut_Gussteil01}, thin wall 25 {= INFO_Breite_Passfedernut_Gussteil01}
    Thickness5: Face (face of Pocket6; face of Pocket6), Thickness 12 {= (INFO_Breite_Passfedernut_Gussteil01 -1mm)/2+FP_cb_Verlaengerung_Fraesung_Passfeder_laengs}
    Fillet5: radius 12 {= (INFO_Breite_Passfedernut_Gussteil01 -1mm)/2}, on edge [face of Pocket6 | face of Pocket6] (x4)
  Assemble7 "key.2": tool Body28, deactivated
  Body29 "key.3"
    Pocket7: profile Sketch17, direction (0, 0, 1), length 10 {= INFO_Tiefe_Passfedernut_Gussteil01}, thin wall 25 {= INFO_Breite_Passfedernut_Gussteil01}
    Thickness6: Face (face of Pocket7; face of Pocket7), Thickness 32 {= (INFO_Breite_Passfedernut_Gussteil01 -1mm)/2+FP_cb_Verlaengerung_Fraesung_Passfeder_quer}
    Fillet6: radius 12 {= (INFO_Breite_Passfedernut_Gussteil01 -1mm)/2}, on edge [face of Pocket7 | face of Pocket7] (x4)
  Assemble8 "key.3": tool Body29
  Body30 "key.4"
    Pocket8: profile Sketch18, direction (0, 0, 1), length 10 {= INFO_Tiefe_Passfedernut_Gussteil01}, thin wall 25 {= INFO_Breite_Passfedernut_Gussteil01}
    Thickness7: Face (face of Pocket8; face of Pocket8), Thickness 32 {= (INFO_Breite_Passfedernut_Gussteil01 -1mm)/2+FP_cb_Verlaengerung_Fraesung_Passfeder_quer}
    Fillet7: radius 12 {= (INFO_Breite_Passfedernut_Gussteil01 -1mm)/2}, on edge [face of Pocket8 | face of Pocket8] (x4)
  Assemble9 "key.4": tool Body30, deactivated
Body31 "SCHIEBERBETT_Gussteil01_Bohrbearbeitung_1"
  Sketch25 on Plane4, origin (1867.5, 326.258, 1433.5), H (1, 0, 0), V (0, -1, 0)
    point P1 (0, 0)
    coincidence: P1 O
  Hole2: placed by Sketch25, at (1867.5, 326.258, 1433.5) direction (0, 0, 1), diameter 10.2, depth 26.3 {= FP_cb_Gewindetiefe+FP_cb_Gewindeauslauf}, V-bottom angle 120, threaded "M12", thread diameter 12, thread depth 18 {= FP_cb_Gewindetiefe}, pitch 1.75
  UserPattern2: of Hole2, copies 4, at the points of Sketch7
Body32 "SCHIEBERBETT_Gussteil01_Bohrbearbeitung_2"
  Sketch26 on Plane4, origin (1850, 326.258, 1433.5), H (1, 0, 0), V (0, -1, 0)
    point P1 (0, 0)
    coincidence: P1 O
  Hole3: placed by Sketch26, at (1850, 326.258, 1433.5) direction (0, 0, 1), diameter 10 {= INFO_D_Passbohrung_Gussteil01}, depth 15 {= FP_cb_Tiefe_Passbohrung}, V-bottom angle 120
  UserPattern3: of Hole3, copies 2, at the points of Sketch8
Body33 "TREIBER_Fertigteil"
  Body34 "Result of cam driver"
    Solid5: linked copy from another document
  Assemble10: tool Body34
  AxisToAxis12: ToTransfor Assemble10, AxisOrigin AxisSystem8, Axis AxisSystem5
Body35 "TREIBER_Gussteil02_Anguss"
  Sketch27 on face of AxisToAxis3, origin (1850, 316.258, 1223.5), H (0, 1, 0), V (0, 0, 1)
    point P1 (10, 0)
    point P2 (-135, 0)
    line L1 (-135, 0) -> (10, 0)
    distance P1 V = 10 {= FP_cd_Ueberstand_Spiegel}
    distance V P2 = 135 {= cd_l+FP_cd_Ueberstand_Spiegel}
    horizontal: L1 H
    coincidence: H L1
  Pad7: profile Sketch27, direction (1, 0, 0), length 40 {= cd_w/2+FP_cd_Ueberstand_Spiegel}, mirrored extent, thin wall 10 {= FP_Aufmass}, second thickness 50
  Chamfer2: length 15 {= FP_cd_Ueberstand_Spiegel +5mm}, angle 45, on edge [face of Pad7 | end face of Pad7] (x2); edge [start face of Pad7 | face of Pad7] (x2)
  Thickness8 "manuelle Korrektur vorn": Face face of Pad7, Thickness 0
  Thickness9 "manuelle Korrektur seitlich": Face (end face of Pad7; start face of Pad7), Thickness 0
  Thickness10 "manuelle Korrektur hinten": Face face of Pad7, Thickness 0
  Body36 "Gussschulter"
    Sketch28 on face of AxisToAxis3, origin (1850, 316.258, 1245.5), H (0, 1, 0), V (0, 0, 1)
      point P1 (0, -50)
      point P2 (0, -82)
      line L1 (0, -82) -> (0, -50)
      distance P2 H = 82 {= FP_cd_Hoehe_Schulter+60mm}
      distance P1 H = 50
      coincidence: V L1
      vertical: L1 V
    Sketch29 on face of AxisToAxis3, origin (1850, 316.258, 1223.5), H (0, 1, 0), V (0, 0, 1)
      point P1 (0, -50)
      point P2 (0, 22)
      line L1 (0, 22) -> (0, -50)
      distance P1 H = 50
      distance H P2 = 22 {= FP_cd_Hoehe_Schulter}
      coincidence: V L1
      vertical: L1 V
    Pad8: profile Sketch29, direction (1, 0, 0), length 30 {= FP_cd_Breite_Schulter /2}, mirrored extent, thin wall 10 {= FP_Aufmass}, second thickness 60
    Pocket9: profile Sketch28, direction (-1, 0, 0), through (limit type 3), opposite side through (limit type 3), thin wall 20, second thickness 50
  Assemble11 "Gussschulter": tool Body36
Body37 "TREIBER_Gussteil02_Fraesbearbeitung_1"
  Body38 "interface"
    Body39
      Sketch30 on face of AxisToAxis3, origin (1850, 316.258, 1223.5), H (0, 1, 0), V (0, 0, 1)
        point P1 (0, 0)
        point P2 (-145, 0)
        line L1 (-145, 0) -> (0, 0)
        distance V P2 = 145 {= cd_l+FP_cd_Ueberstand_Spiegel +10mm}
        horizontal: L1 H
        coincidence: H L1, V P1
      Pocket10: profile Sketch30, direction (-1, 0, 0), length 55 {= cd_w /2+FP_cd_Ueberstand_Spiegel +15mm}, mirrored extent, thin wall 110 {= FP_Aufmass + FP_cd_Fraeshoehe}
      Fillet8: radius 20, on edge [end face of Pocket10 | face of Pocket10] (x2); edge [face of Pocket10 | start face of Pocket10] (x2)
    Assemble12: tool Body39
    Body40
      Sketch31 on face of AxisToAxis3, origin (1850, 316.258, 1223.5), H (0, 1, 0), V (0, 0, 1)
        point P1 (0, 0)
        point P2 (0, 32)
        line L1 (0, 32) -> (0, 0)
        distance H P2 = 32 {= FP_cd_Hoehe_Schulter +10mm}
        coincidence: V P1
        vertical: L1 V
      Pocket11: profile Sketch31, direction (-1, 0, 0), length 55 {= FP_cd_Breite_Schulter  /2+FP_cd_Ueberstand_Spiegel +15mm}, mirrored extent, thin wall 30 {= FP_Aufmass +20mm}
      Fillet9: radius 20, on edge [face of Pocket11 | end face of Pocket11]; edge [start face of Pocket11 | face of Pocket11]
    Assemble13: tool Body40
  Assemble14 "interface": tool Body38
  Body41 "key.5"
    Sketch32 "SKETCH_Passfeder5" on Plane5, origin (1885, 286.258, 1223.5), H (0, -1, 0), V (-1, 0, 0)
      line L1 (0, -25) -> (0, 25)
      length L1 = 50 {= cd_kc_l}
      midpoint: L1 O
      vertical: L1 V
    Pocket12: profile Sketch32, direction (0, 0, -1), length 10 {= INFO_Tiefe_Passfedernut_Gussteil01}, thin wall 25 {= INFO_Breite_Passfedernut_Gussteil01}
    Thickness11: Face (face of Pocket12; face of Pocket12), Thickness 32 {= (INFO_Breite_Passfedernut_Gussteil01 -1mm)/2+FP_cd_Verlaengerung_Fraesung_Passfeder_quer}
    Fillet10: radius 12 {= (INFO_Breite_Passfedernut_Gussteil01 -1mm)/2}, on edge [face of Pocket12 | face of Pocket12] (x4)
  Assemble15 "key.5": tool Body41, deactivated
  Body42 "key.6"
    Sketch33 "SKETCH_Passfeder6" on Plane5, origin (1815, 286.258, 1223.5), H (0, -1, 0), V (-1, 0, 0)
      line L1 (0, -25) -> (0, 25)
      length L1 = 50 {= cd_kc_l}
      midpoint: L1 O
      vertical: L1 V
    Pocket13: profile Sketch33, direction (0, 0, -1), length 10 {= INFO_Tiefe_Passfedernut_Gussteil01}, thin wall 25 {= INFO_Breite_Passfedernut_Gussteil01}
    Thickness12: Face (face of Pocket13; face of Pocket13), Thickness 32 {= (INFO_Breite_Passfedernut_Gussteil01 -1mm)/2+FP_cd_Verlaengerung_Fraesung_Passfeder_quer}
    Fillet11: radius 12 {= (INFO_Breite_Passfedernut_Gussteil01 -1mm)/2}, on edge [face of Pocket13 | face of Pocket13] (x4)
  Assemble16 "key.6": tool Body42, deactivated
Body43 "TREIBER_Gussteil02_Bohrbearbeitung_1"
  Sketch34 on Plane5, origin (1867.5, 306.258, 1223.5), H (1, 0, 0), V (0, 1, 0)
    point P1 (0, 0)
    coincidence: P1 O
  Hole4: placed by Sketch34, at (1867.5, 306.258, 1223.5) direction (0, 0, -1), diameter 8.5, depth 22.3 {= FP_cd_Gewindetiefe+FP_cd_Gewindeauslauf}, V-bottom angle 120, threaded "M10", thread diameter 10, thread depth 15 {= FP_cd_Gewindetiefe}, pitch 1.5
  UserPattern4: of Hole4, copies 3, at the points of Sketch10
Body44 "TREIBER_Gussteil02_Bohrbearbeitung_2"
  Sketch35 on Plane5, origin (1850, 306.258, 1223.5), H (1, 0, 0), V (0, 1, 0)
    point P1 (0, 0)
    coincidence: P1 O
  Hole5: placed by Sketch35, at (1850, 306.258, 1223.5) direction (0, 0, -1), diameter 10 {= INFO_D_Passbohrung_Gussteil02}, depth 15 {= FP_cd_Tiefe_Passbohrung}, V-bottom angle 120
  UserPattern5: of Hole5, copies 2, at the points of Sketch11
Body45 "SCHIEBER_Montagefreiraum"
  Body46 "Result of mounting clearance"
    Solid6: linked copy from another document
  Assemble17: tool Body46
  AxisToAxis13: ToTransfor Assemble17, AxisOrigin AxisSystem8, Axis AxisSystem5
Body47 "SCHIEBER_Bauraum"
Relations
  design table, configuration 439, drives INFO_Version_Ausgabe, INFO_Schieberhub, INFO_Winkel_Arbeitsrichtung, INFO_Winkel_Alpha, INFO_Passfeder_im_Lieferumfang, INFO_Winkel_Treiber, INFO_Winkel_Schieberbett, INFO_Schieberart, INFO_Tol_Passung_Gusstei02, INFO_Breite_Passfedernut_Gussteil01, INFO_Gewinde_Gussteil01, INFO_D_Passbohrung_Gussteil01, INFO_Tol_Passung_Gussteil01, INFO_Gewinde_Gussteil02, INFO_D_Passbohrung_Gussteil02, INFO_Tiefe_Passfedernut_Gussteil01, INFO_Tol_Passfedernut_Gussteil01, cb_l, cb_w, FP_cb_Hoehe_Schulter, FP_cb_Breite_Schulter, cd_l, cd_w, FP_cd_Hoehe_Schulter, FP_cd_Breite_Schulter, factor, sp, ss, cb_kl_h, cb_kl_t, cb_kl_l, cb_kl1_x, cb_kl1_activity, cb_kl2_x, cb_kl2_activity, cb_kc_l, cb_kc1_x, cb_kc1_y, cb_kc1_activity, cb_kc2_activity, cd_kc_l, cd_kc1_x, cd_kc1_y, cd_kc1_activity, cd_kc2_activity, type, Produktbezeichnung, Werkstoff_Benennung, Rohmass, Zusatzinfo, Rohmasse, arx, ary, arz
  Assemble3.Activity = cb_backup_thrust
  Pocket2.Activity = cb_clearance_backup_thrust
  Assemble11.Activity = cd_backup_thrust
  Pocket9.Activity = cd_clearance_backup_thrust
  Hole2.ThreadDescription = INFO_Gewinde_Gussteil01
  Hole4.ThreadDescription = INFO_Gewinde_Gussteil02
  Pad1.Activity = cb_kl1_activity
  Pad2.Activity = cb_kl2_activity
  Pad3.Activity = cb_kc1_activity
  Pad4.Activity = cb_kc2_activity
  Assemble6.Activity = cb_kl1_activity
  Assemble7.Activity = cb_kl2_activity
  Assemble8.Activity = cb_kc1_activity
  Assemble9.Activity = cb_kc2_activity
  Assemble15.Activity = cd_kc1_activity
  Assemble16.Activity = cd_kc2_activity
